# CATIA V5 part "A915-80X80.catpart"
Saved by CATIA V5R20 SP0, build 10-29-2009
Part number: A915-80X80
Source: Unknown
Property "A": "0.000"
Property "ARTICLENO": "A915-80X80"
Property "BOMINFO": "A915-80X80"
Property "CODE": "A915-80X80"
Property "CREATOR": "CADENAS GmbH"
Property "D": "13.500"
Property "D1": "20.000"
Property "FORM": "B"
Property "L": "80.000"
Property "L1": "25.000"
Property "L2": "30.000"
Property "LINA": "A915-80X80"
Property "NB": "A915-80X80"
Property "NBSYN": "$CODE."
Property "NN": "A915"
Property "NT": "VDI 3357 Wear Plates, steel"
Property "SCREW": "M12x25"
Property "SUPPLIER": "CF"
Property "T": "13.000"
Property "W": "80.000"
Bounding box of the stored display mesh (mm): x 0 to 20, y 0 to 80, z -40 to 40
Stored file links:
  C:\Users\borellobunino\Desktop\3D X SITO CF\A915\GSB_OILLESS_G22501080080\A915-80X80.catpart
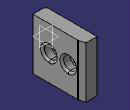
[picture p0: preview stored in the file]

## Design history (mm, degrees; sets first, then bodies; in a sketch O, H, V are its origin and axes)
Body1 "Geometry.1" (main body)
  Solid1 "A915-80X80.catpart": solid without history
